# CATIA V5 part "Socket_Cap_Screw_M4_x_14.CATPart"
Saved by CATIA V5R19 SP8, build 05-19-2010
Part number: Socket Cap Screw M4 x 14
Definition: 70555
Material "Chrome": density 7190 kg/m3, Young's modulus 7e+10 Pa, Poisson ratio 0.3, thermal expansion 6.2e-06 1/K
Bounding box of the stored display mesh (mm): x -4.195 to 4.195, y -4.199 to 4.199, z -2.918 to 14
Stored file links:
  D:\Documents\1_Travail\1 - ac-limoges.fr\ac-limoges.fr\Emmanuel Maynard - STI2D_Turgot\1 - IT-I2D\Activités_IT_Première\IT_3_Abris_bus\Maquettes numériques\Abribus_eleve\Socket_Cap_Screw_M4_x_14.CATPart
  C:\Program Files\Dassault Systemes\B19\win_b64\startup\materials\French\Catalog.CATMaterial
  C:\Program Files\Dassault Systemes\B19\win_b64\reffiles\standard\MetricThickPitch.txt
  D:\Documents\1_Travail\2- 2I2D\6 -  Ressources ITEC\Ressources Techniques\0-Maquettes numériques_Composants\Catalogue_Makeblock\Catalog_Makeblock\08_Visserie\Table Vis bombeesM4.xls
  D:\Documents\1_Travail\2- 2I2D\6 -  Ressources ITEC\Ressources Techniques\0-Maquettes numériques_Composants\Catalogue_Makeblock\Catalog_Makeblock\08_Visserie\Table Vis bombeesM4.txt
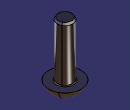
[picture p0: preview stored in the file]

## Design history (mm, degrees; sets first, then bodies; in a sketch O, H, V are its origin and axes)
Parameters
  Longueur = 14 mm
  `Longueur filetée` = 14 mm
  `Désignation` = "Socket Cap Screw M4 x 14"
  `Référence` = "70555"
AxisSystem1: origin (0, 0, 0), X (1, 0, 0), Y (0, 1, 0), Z (0, 0, 1)
Body1 (main body), material "Chrome"
  Sketch1 on ZX plane of AxisSystem1, origin (0, 0, 0), H (0, 0, 1), V (1, 0, 0)
    point P1 (0, 4.2)
    line L1 (0, 4.2) -> (0, 2)
    line L2 (0, 2) -> (14, 2)
    line L3 (14, 2) -> (14, 0)
    point P4 (14, 0)
    point P5 (1.2952, 0)
    axis line L4 (-59.0265, 0) -> (107.0959, 0)
    point P6 (-59.0265, 0)
    point P8 (-3.1, 0)
    arc A1 centre (1.2952, 0) radius 4.3952 from (0, 4.2) to (-3.1, 0) ccw
    distance L2 L4 = 2
    distance L3 L1 = 14 {= Longueur}
    distance P8 L1 = 3.1
    distance P1 L4 = 4.2
    coincidence: P1 V, P4 H, P5 H, P6 H, L4 P8
    vertical: L1 V, L3 V
    horizontal: L2 H, L4 H
  Shaft1: profile Sketch1, axis Sketch1.L4, angle 360
  Fillet1: radius 0.2, on edge [face of Shaft1 from Sketch1.L1 | face of Shaft1 from Sketch1.L2]
  Body2
    Sketch2 on XY plane of AxisSystem1, origin (0, 0, 0), H (1, 0, 0), V (0, 1, 0)
      point P1 (0.7217, 1.25)
      point P2 (-0.7217, 1.25)
      point P3 (-1.4434, 0)
      point P4 (-0.7217, -1.25)
      point P5 (0.7217, -1.25)
      point P6 (1.4434, 0)
      point P7 (0, 1.25)
      line L1 (0.7217, 1.25) -> (-0.7217, 1.25)
      line L2 (-0.7217, 1.25) -> (-1.4434, 0)
      line L3 (-1.4434, 0) -> (-0.7217, -1.25)
      line L4 (-0.7217, -1.25) -> (0.7217, -1.25)
      line L5 (0.7217, -1.25) -> (1.4434, 0)
      line L6 (1.4434, 0) -> (0.7217, 1.25)
      construction line L7 (0, 0) -> (0, 1.25)
      construction circle A1 centre (0, 0) radius 1.4434
      construction arc A2 centre (0.7217, -1.25) radius 1.4434 from (-0.7217, -1.25) to (1.4434, 0) cw
      construction arc A3 centre (-0.7217, 1.25) radius 1.4434 from (-1.4434, 0) to (0.7217, 1.25) ccw
      distance L5 L2 = 2.5
      vertical: L7 V
      coincidence: A1 P1, A1 P2, A1 P3, A1 P4, A1 P5, A1 P6, A2 O, A3 O
      midpoint: P7 L1
      parallelism: L1 L4
    Pad1: profile Sketch2, direction (0, 0, -1), length 5
    Chamfer1: length 1.2, angle 30, on start face of Pad1
  Remove1: tool Body2
  Thread1: "M4", diameter 4, depth 14 {= `Longueur filetée`}, pitch 0.7, on face of Shaft1 from Sketch1.L2, from face of Shaft1 from Sketch1.L3
  Chamfer2: length 0.5, angle 30, on edge [face of Shaft1 from Sketch1.L2 | face of Shaft1 from Sketch1.L3]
